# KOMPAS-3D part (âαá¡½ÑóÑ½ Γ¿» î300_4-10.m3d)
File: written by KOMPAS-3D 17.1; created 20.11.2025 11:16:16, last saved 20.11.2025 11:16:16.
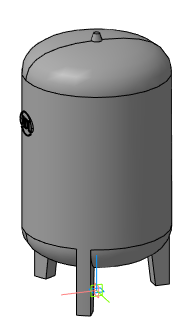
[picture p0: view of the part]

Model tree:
1. Операция без истории:3

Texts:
  REVIT MATERIAL OVERRIDDEN
  REVIT MATERIAL ID
  REVIT SUBCATEGORY ID
  REVIT CATEGORY ID
  REVIT ELEMENT ID
  REVIT BREP TAG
